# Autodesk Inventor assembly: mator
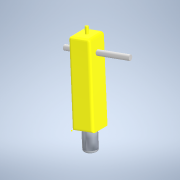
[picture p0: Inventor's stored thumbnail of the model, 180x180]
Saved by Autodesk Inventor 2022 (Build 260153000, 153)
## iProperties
Created: 2021-07
Part Number: mator
Document SubType Name: Assembly
Designer: Chimms
Author: Chimms
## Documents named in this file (3)
- C:\Users\Chimms\Documents\New folder (2)\mator.iam
- C:\Users\Chimms\Documents\New folder (2)\rod.ipt
- C:\Users\Chimms\Documents\motorlafda.ipt
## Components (2 placed, 2 different names)
1. rod:1 — Rotational:1
2. motorlafda:1 — Rotational:1
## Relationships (1: RevoluteJoint 1)
- Rotational:1 [RevoluteJoint]: rod:1 ↔ motorlafda:1
